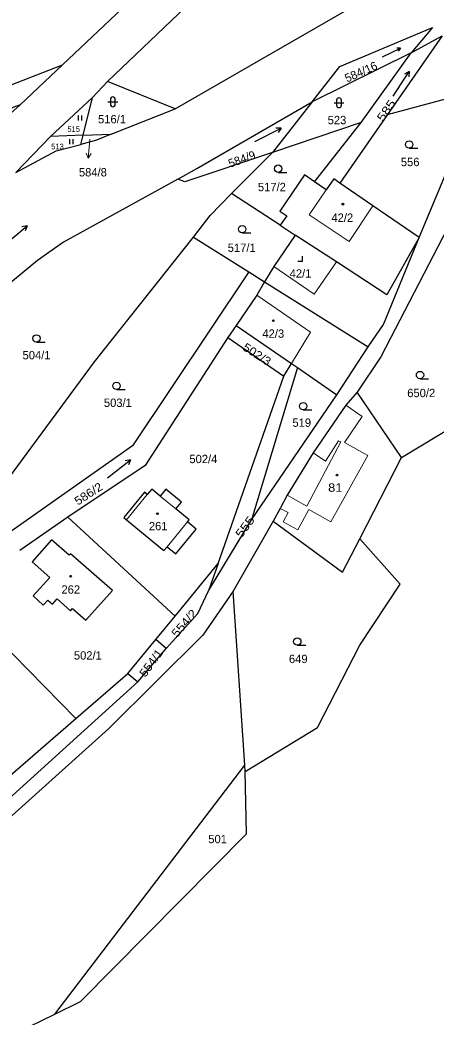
# Model space of a CAD drawing. Extents: x -754445 to -751443, y -1030748 to -1028224.
# Drawn here: x -752647.9 to -752563.3, y -1028727.9 to -1028524.8 of the extents above; entities that cross this region are included whole.
import ezdxf
from ezdxf.enums import TextEntityAlignment as Align

# ---------------------------------------------------------------- set-up
doc = ezdxf.new("R2010")
doc.units = 0
doc.header["$LTSCALE"] = 0.68
for name, color, linetype, lineweight in [('1', 7, 'Continuous', 25), ('3', 7, 'Continuous', 25), ('4', 7, 'Continuous', 13), ('5', 7, 'Continuous', 25), ('7', 7, 'Continuous', 13)]:
    doc.layers.add(name, color=color, linetype=linetype, lineweight=lineweight)
doc.layers.add('2', color=7, linetype='Continuous')

msp = doc.modelspace()

# ---------------------------------------------------------------- linework, layer by layer
at = {"layer": '1'}
for p, q in [((-752639.29, -1028533.95), (-752588.3, -1028485.62)), ((-752616.34, -1028542.9), (-752546.71, -1028502.68)), ((-752562, -1028528.01), (-752573.14, -1028544.06)), ((-752578.51, -1028545.71), (-752568.35, -1028531.48)), ((-752675.98, -1028548.14), (-752639.29, -1028533.95)), ((-752639.29, -1028533.95), (-752647.89, -1028542.1)), ((-752633.21, -1028540.57), (-752641.73, -1028548.5)), ((-752635.08, -1028548.27), (-752633.21, -1028540.57)), ((-752573.14, -1028544.06), (-752582.84, -1028558.02)), ((-752635.08, -1028548.27), (-752629.37, -1028548.07)), ((-752594.97, -1028566.61), (-752604.89, -1028560.11)), ((-752612.65, -1028569.04), (-752601.4, -1028576.11)), ((-752601.4, -1028576.11), (-752598.15, -1028578.14)), ((-752598.15, -1028578.14), (-752577.06, -1028591.36)), ((-752603.96, -1028586.99), (-752605.66, -1028589.46)), ((-752605.66, -1028589.46), (-752594.25, -1028597.32)), ((-752583.43, -1028601.13), (-752577.06, -1028591.36)), ((-752591.48, -1028595.59), (-752600.82, -1028626.57)), ((-752594.25, -1028597.32), (-752592.7, -1028594.75)), ((-752607.61, -1028635.49), (-752594.25, -1028597.32)), ((-752600.82, -1028626.57), (-752583.43, -1028601.13)), ((-752596.39, -1028626.85), (-752604.55, -1028641.14)), ((-752641.52, -1028630.66), (-752645.48, -1028635.18)), ((-752616.39, -1028646.2), (-752607.61, -1028635.49)), ((-752660.36, -1028642.84), (-752636.55, -1028667.05)), ((-752620.32, -1028650.99), (-752616.39, -1028646.2)), ((-752625.97, -1028657.89), (-752623.97, -1028659.58)), ((-752655.45, -1028683.4), (-752636.55, -1028667.05))]:
    msp.add_line(p, q, dxfattribs=at)
for points in [[(-752552.32, -1028462.48), (-752586.88, -1028495.96), (-752630.14, -1028537.36)], [(-752588.45, -1028541.44), (-752582.84, -1028534.3), (-752564.01, -1028526.31), (-752568.35, -1028531.48), (-752562, -1028528.01)], [(-752568.35, -1028531.48), (-752588.45, -1028541.44), (-752596.56, -1028551.8)], [(-752573.14, -1028544.06), (-752553.22, -1028538.7), (-752541.84, -1028531.39), (-752537.05, -1028531.43)], [(-752566.71, -1028569.1), (-752555.97, -1028543.44), (-752537.05, -1028531.43)], [(-752629.37, -1028548.07), (-752616.34, -1028542.9), (-752630.14, -1028537.36), (-752633.21, -1028540.57)], [(-752615.82, -1028557.2), (-752611.98, -1028555.08), (-752588.45, -1028541.44)], [(-752660.8, -1028553.56), (-752647.89, -1028542.1), (-752678.35, -1028553.28), (-752680.33, -1028553.6)], [(-752588, -1028557.75), (-752578.51, -1028545.71), (-752596.56, -1028551.8)], [(-752635.53, -1028550.14), (-752635.08, -1028548.27), (-752641.73, -1028548.5), (-752648.81, -1028555.83)], [(-752629.37, -1028548.07), (-752632.36, -1028549.31), (-752635.53, -1028550.14)], [(-752648.81, -1028555.83), (-752640.58, -1028551.45), (-752635.53, -1028550.14)], [(-752596.56, -1028551.8), (-752614.37, -1028557.79), (-752615.82, -1028557.2)], [(-752612.65, -1028569.04), (-752609.27, -1028564.65), (-752604.89, -1028560.11), (-752596.56, -1028551.8)], [(-752615.82, -1028557.2), (-752639.06, -1028570.02), (-752644.39, -1028573.79), (-752651, -1028579.31), (-752657.18, -1028586.51), (-752663.11, -1028596.69), (-752671.81, -1028613.68), (-752656.24, -1028626.23)], [(-752588, -1028557.75), (-752590.03, -1028556.36), (-752595.09, -1028563.72), (-752593.66, -1028564.7), (-752594.97, -1028566.61), (-752591.92, -1028568.6)], [(-752582.84, -1028558.02), (-752584.09, -1028557.16), (-752585.62, -1028559.39), (-752588, -1028557.75)], [(-752566.71, -1028569.1), (-752576.13, -1028562.63), (-752582.84, -1028558.02)], [(-752560.97, -1028567.23), (-752574.53, -1028593.42), (-752579.3, -1028600.61)], [(-752656.24, -1028626.23), (-752632.77, -1028594.44), (-752612.65, -1028569.04)], [(-752591.92, -1028568.6), (-752596.31, -1028575), (-752598.15, -1028578.14)], [(-752566.71, -1028569.1), (-752573.32, -1028580.76), (-752583.55, -1028574.07), (-752591.92, -1028568.6)], [(-752577.06, -1028591.36), (-752574, -1028586.8), (-752566.71, -1028569.1)], [(-752601.4, -1028576.11), (-752625.05, -1028611.51), (-752651.4, -1028630.13)], [(-752598.15, -1028578.14), (-752599.74, -1028580.84), (-752603.96, -1028586.99), (-752592.7, -1028594.75), (-752591.48, -1028595.59), (-752583.43, -1028601.13)], [(-752605.66, -1028589.46), (-752622.5, -1028615.52), (-752638.21, -1028626.08)], [(-752570.3, -1028613.88), (-752558.49, -1028606.79), (-752540.12, -1028590.16)], [(-752579.3, -1028600.61), (-752581.6, -1028603.27), (-752588.25, -1028612.96), (-752593.54, -1028621.56), (-752594.99, -1028624.28), (-752596.39, -1028626.85)], [(-752578.81, -1028630.45), (-752570.3, -1028613.88), (-752579.3, -1028600.61)], [(-752616.39, -1028646.2), (-752638.21, -1028626.08), (-752648, -1028632.86)], [(-752607.61, -1028635.49), (-752609.56, -1028641.07), (-752600.82, -1028626.57)], [(-752596.39, -1028626.85), (-752582.3, -1028637.26), (-752578.81, -1028630.45)], [(-752645.48, -1028635.18), (-752641.86, -1028638.32), (-752645.23, -1028642.09), (-752643.21, -1028643.99), (-752642.24, -1028642.96), (-752641.33, -1028643.76), (-752640.4, -1028642.7), (-752637.64, -1028645.11), (-752637.24, -1028644.66), (-752634.56, -1028647.03), (-752629.13, -1028641), (-752637.67, -1028633.53), (-752637.91, -1028633.79), (-752641.52, -1028630.66)], [(-752602.11, -1028677.84), (-752587.41, -1028668.89), (-752578.77, -1028652.12), (-752570.6, -1028639.7), (-752578.81, -1028630.45)], [(-752604.55, -1028641.14), (-752610.72, -1028650.07), (-752629.83, -1028669.09), (-752660.44, -1028696.62), (-752680.04, -1028709.72), (-752695.17, -1028719.5), (-752712.78, -1028733.15), (-752746.31, -1028767.61), (-752784.35, -1028811.55)], [(-752705.38, -1028792.18), (-752702.03, -1028786.31), (-752689.9, -1028758.48), (-752679.94, -1028746.27), (-752640.88, -1028727.28), (-752602.19, -1028676.58), (-752604.55, -1028641.14)], [(-752618.2, -1028652.78), (-752611.76, -1028645.67), (-752609.56, -1028641.07)], [(-752636.55, -1028667.05), (-752625.97, -1028657.89), (-752620.32, -1028650.99)], [(-752623.97, -1028659.58), (-752618.2, -1028652.78), (-752620.32, -1028650.99)], [(-752681.94, -1028707.94), (-752663.37, -1028695.29), (-752623.97, -1028659.58)], [(-752640.88, -1028727.28), (-752635.63, -1028724.72), (-752601.82, -1028690.53), (-752602.11, -1028677.84), (-752602.19, -1028676.58)]]:
    msp.add_lwpolyline(points, dxfattribs=at)
msp.add_lwpolyline([(-752616.23, -1028633.52), (-752612.1, -1028628.5), (-752613.88, -1028627.04), (-752613.52, -1028626.6), (-752616.22, -1028624.38), (-752615.07, -1028622.98), (-752618.24, -1028620.37), (-752619.4, -1028621.78), (-752621.14, -1028620.35), (-752622.03, -1028621.43), (-752622.57, -1028620.99), (-752626.81, -1028626.16), (-752626.27, -1028626.6), (-752618.64, -1028632.84), (-752618, -1028632.07)], close=True, dxfattribs=at)
at = {"layer": '3'}
for p, q in [((-752570.541, -1028530.529), (-752570.982, -1028531.118)), ((-752568.73, -1028535.284), (-752568.841, -1028536.377)), ((-752629.541, -1028540.971), (-752629.541, -1028541.972)), ((-752628.539, -1028541.972), (-752628.539, -1028540.971)), ((-752583.531, -1028541.151), (-752583.531, -1028542.152)), ((-752582.529, -1028542.152), (-752582.529, -1028541.151)), ((-752630.041, -1028541.471), (-752628.039, -1028541.471)), ((-752584.031, -1028541.651), (-752582.029, -1028541.651)), ((-752636.022, -1028545.24), (-752636.022, -1028544.235)), ((-752635.352, -1028545.24), (-752635.352, -1028544.235)), ((-752594.788, -1028546.848), (-752595.431, -1028547.738)), ((-752637.772, -1028550.1), (-752637.772, -1028549.095)), ((-752637.102, -1028550.1), (-752637.102, -1028549.095)), ((-752568.743, -1028550.91), (-752566.993, -1028550.91)), ((-752595.393, -1028555.83), (-752593.643, -1028555.83)), ((-752646.463, -1028566.707), (-752646.889, -1028567.719)), ((-752602.743, -1028568.15), (-752600.993, -1028568.15)), ((-752644.593, -1028590.4), (-752642.843, -1028590.4)), ((-752566.533, -1028597.86), (-752564.783, -1028597.86)), ((-752628.293, -1028600.05), (-752626.543, -1028600.05)), ((-752590.323, -1028604.2), (-752588.573, -1028604.2)), ((-752625.427, -1028614.379), (-752625.888, -1028615.376)), ((-752591.513, -1028652.14), (-752589.763, -1028652.14))]:
    msp.add_line(p, q, dxfattribs=at)
for points in [[(-752574.154, -1028532.291), (-752570.541, -1028530.529), (-752571.276, -1028530.514)], [(-752571.997, -1028540.316), (-752568.73, -1028535.284), (-752569.682, -1028535.831)], [(-752600.134, -1028549.572), (-752594.788, -1028546.848), (-752595.886, -1028546.845)], [(-752651.059, -1028570.564), (-752646.463, -1028566.707), (-752647.534, -1028566.951)], [(-752591.431, -1028573.92), (-752590.43, -1028573.92), (-752590.43, -1028572.92)], [(-752630.155, -1028618.073), (-752625.427, -1028614.379), (-752626.506, -1028614.586)]]:
    msp.add_lwpolyline(points, dxfattribs=at)
for centre in [(-752568.7429, -1028550.1598), (-752595.3929, -1028555.0798), (-752602.7429, -1028567.3998), (-752644.5929, -1028589.6498), (-752566.5329, -1028597.1098), (-752628.2929, -1028599.2998), (-752590.3229, -1028603.4498), (-752591.5129, -1028651.3898)]:
    msp.add_circle(centre, 0.75, dxfattribs=at)
for centre, start, end in [((-752629.04, -1028540.9709), 0, 180), ((-752583.03, -1028541.1509), 0, 180), ((-752629.04, -1028541.9709), 180, 359.98789), ((-752583.03, -1028542.1509), 180, 359.98789)]:
    msp.add_arc(centre, 0.5, start, end, dxfattribs=at)
at = {"layer": '4'}
for p, q in [((-752589.11, -1028564.46), (-752585.62, -1028559.39)), ((-752576.13, -1028562.63), (-752580.97, -1028569.89)), ((-752589.11, -1028564.46), (-752580.97, -1028569.89)), ((-752596.31, -1028575), (-752588.07, -1028580.66)), ((-752583.55, -1028574.07), (-752588.07, -1028580.66)), ((-752588.85, -1028588.38), (-752599.74, -1028580.84)), ((-752592.7, -1028594.75), (-752588.85, -1028588.38)), ((-752578.3, -1028605.53), (-752581.6, -1028603.27)), ((-752578.3, -1028605.53), (-752581.87, -1028610.87)), ((-752583.14, -1028610.48), (-752585.78, -1028614.65)), ((-752583.14, -1028610.48), (-752582.63, -1028610.75)), ((-752589.57, -1028623.8), (-752582.63, -1028610.75)), ((-752577.16, -1028613.48), (-752581.87, -1028610.87)), ((-752585.78, -1028614.65), (-752588.25, -1028612.96)), ((-752577.16, -1028613.48), (-752584.66, -1028627.01)), ((-752626.27, -1028626.6), (-752622.03, -1028621.43)), ((-752619.4, -1028621.78), (-752616.22, -1028624.38)), ((-752589.57, -1028623.8), (-752593.54, -1028621.56)), ((-752594.99, -1028624.28), (-752593.39, -1028625.14)), ((-752589.14, -1028624.53), (-752591.37, -1028628.64)), ((-752584.66, -1028627.01), (-752589.14, -1028624.53)), ((-752593.39, -1028625.14), (-752594.4, -1028627)), ((-752618, -1028632.07), (-752613.88, -1028627.04)), ((-752594.4, -1028627), (-752591.37, -1028628.64))]:
    msp.add_line(p, q, dxfattribs=at)
at = {"layer": '5'}
for centre in [(-752582.2268, -1028562.3092), (-752596.3768, -1028586.0392), (-752583.4368, -1028617.4992), (-752619.9768, -1028625.3492), (-752637.6168, -1028638.0892)]:
    msp.add_circle(centre, 0.175, dxfattribs=at)
at = {"layer": '7'}
msp.add_line((-752634.072, -1028552.95), (-752633.485, -1028551.996), dxfattribs=at)
msp.add_lwpolyline([(-752633.72, -1028549.07), (-752633.81, -1028549.96), (-752634.072, -1028552.95), (-752634.483, -1028551.908)], dxfattribs=at)

# ---------------------------------------------------------------- texts
at = {"layer": '2'}
for s, rotation, p in [('584/16', 24, (-752578.2032, -1028536.1437)), ('584/9', 20, (-752602.5052, -1028553.938))]:
    msp.add_text(s, height=1.7, rotation=rotation, dxfattribs=at).set_placement(p, align=Align.CENTER)
for s, rotation, width, p in [('585', 55, 1.25, (-752572.7059, -1028543.7125)), ('502/3', 327, 1.1, (-752600.1734, -1028593.5929)), ('586/2', 33, 1.1, (-752633.5484, -1028622.0121)), ('555', 53, 1.25, (-752601.4733, -1028628.5395)), ('554/2', 49, 1.15, (-752613.8643, -1028648.2351)), ('554/1', 54, 1.1, (-752620.5801, -1028656.2566))]:
    msp.add_text(s, height=1.7, rotation=rotation, dxfattribs=dict(at, width=width)).set_placement(p, align=Align.CENTER)
for s, height, p in [('516/1', 1.7, (-752629.21, -1028545.85)), ('523', 1.7, (-752583.429, -1028546.03)), ('515', 1.14, (-752637.02, -1028547.58)), ('513', 1.14, (-752640.31, -1028551.13)), ('556', 1.7, (-752568.539, -1028554.57)), ('517/2', 1.7, (-752596.68, -1028559.67)), ('42/2', 1.7, (-752582.35, -1028565.91)), ('517/1', 1.7, (-752602.82, -1028572.04)), ('42/1', 1.7, (-752590.85, -1028577.28)), ('42/3', 1.7, (-752596.4, -1028589.52)), ('504/1', 1.7, (-752644.57, -1028593.91)), ('650/2', 1.7, (-752566.29, -1028601.62)), ('503/1', 1.7, (-752628.02, -1028603.61)), ('519', 1.7, (-752590.599, -1028607.66)), ('502/4', 1.7, (-752610.62, -1028615.06)), ('261', 1.7, (-752619.819, -1028628.73)), ('262', 1.7, (-752637.609, -1028641.65)), ('502/1', 1.7, (-752634.13, -1028655.07)), ('649', 1.7, (-752591.319, -1028655.78)), ('501', 1.7, (-752607.729, -1028692.47))]:
    msp.add_text(s, height=height, dxfattribs=at).set_placement(p, align=Align.CENTER)
msp.add_text('584/8', height=1.7, dxfattribs=at).set_placement((-752630.259, -1028556.663), align=Align.RIGHT)
at = {"layer": '2', "width": 1.15}
msp.add_text('81', height=1.7, dxfattribs=at).set_placement((-752583.78, -1028620.89), align=Align.CENTER)

doc.saveas('drawing.dxf')
